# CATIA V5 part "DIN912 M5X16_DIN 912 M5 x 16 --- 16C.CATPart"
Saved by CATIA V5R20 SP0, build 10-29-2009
Part number: DIN912 M5X16_DIN 912 M5 x 16 --- 16C
Revision: ANY
Definition: UNKNOWN
Nomenclature: DIN912 M5X16_DIN 912 M5 x 16 --- 16C
Source: Unknown
Bounding box of the stored display mesh (mm): x 0 to 21, y -4.25 to 4.25, z -4.25 to 4.25
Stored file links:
  C:\Users\Utente\Desktop\IO LAVORO\3D X SITO CF\CUMSA\3D files CG\CG 604035\DIN912 M5X16_DIN 912 M5 x 16 --- 16C.CATPart
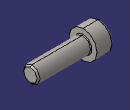
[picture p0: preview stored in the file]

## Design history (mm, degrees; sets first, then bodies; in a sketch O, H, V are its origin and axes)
Body1 "Hex" (main body)
  Solid1: solid without history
